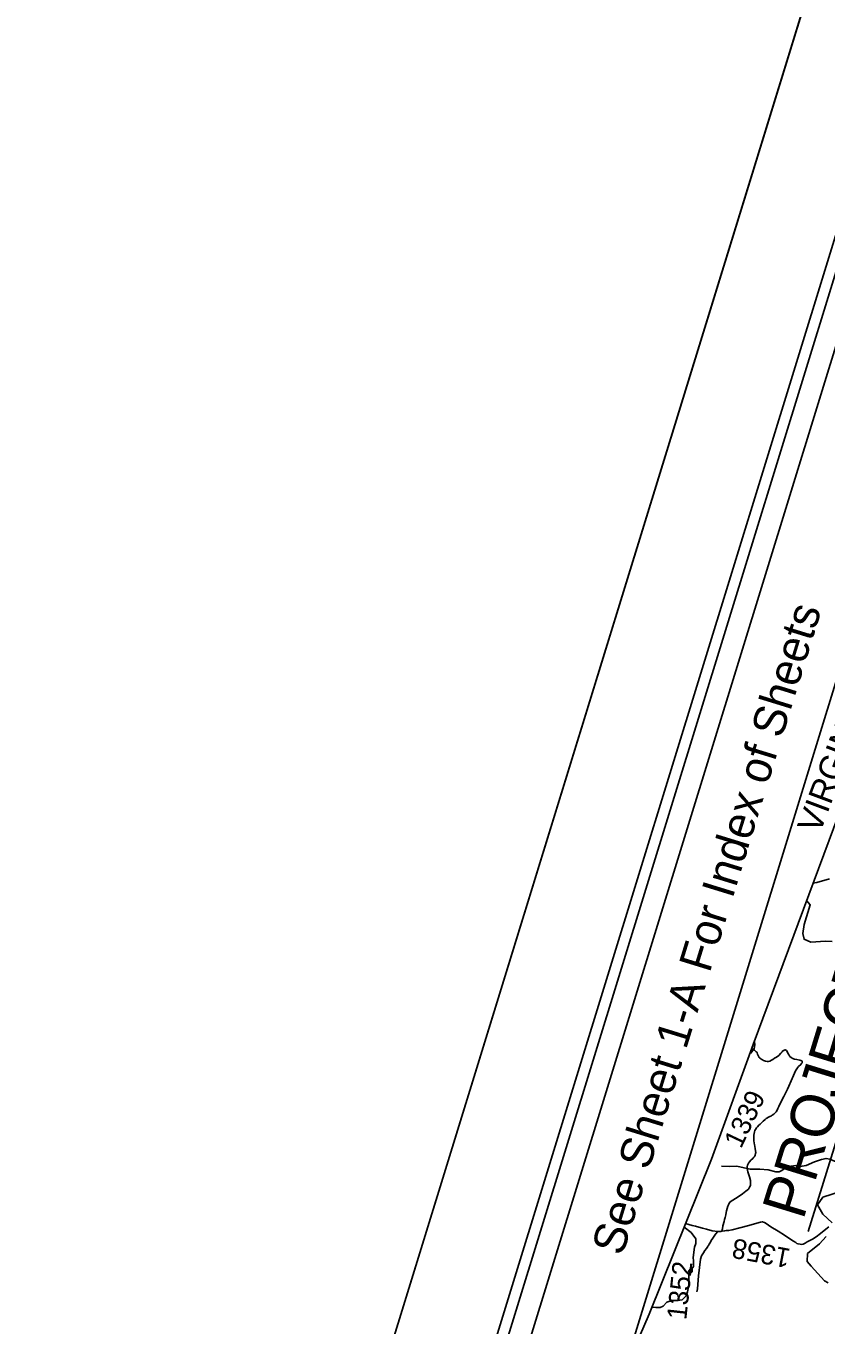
# Model space of a CAD drawing. Extents: x 1347947 to 1350662, y 1027710 to 1030532.
# Drawn here: x 1347946.9 to 1348130.6, y 1028835.1 to 1029133.4 of the extents above; entities that cross this region are included whole.
import ezdxf

# ---------------------------------------------------------------- set-up
doc = ezdxf.new("R2010")
doc.units = 0
for name, color, linetype in [('Default', 7, 'Continuous'), ('Prop Leader Line Light', 7, 'Continuous'), ('Prop Leader Line Medium', 7, 'Continuous'), ('Prop WCC CELL', 7, 'Continuous'), ('Sheet Cutting Line CELL', 7, 'Continuous'), ('Sheet Data Field CELL', 7, 'Continuous'), ('Sheet Plot Border Inside CELL', 7, 'Continuous'), ('Sheet Plot Border Outside CELL', 7, 'Continuous'), ('Sheet Title CELL', 7, 'Continuous')]:
    doc.layers.add(name, color=color, linetype=linetype)

msp = doc.modelspace()

# ---------------------------------------------------------------- linework, layer by layer
at = {"layer": 'Default'}
msp.add_line((1348099.77, 1028848.03), (1348099.39, 1028847.22), dxfattribs=at)
for points in [[(1348083.52, 1028822.71), (1348089.97, 1028837.63), (1348104.26, 1028873.21), (1348113.82, 1028899.5), (1348162.49, 1029030.38), (1348171.57, 1029045.86), (1348180.52, 1029067.26), (1348186.85, 1029082.58), (1348194.68, 1029101.03), (1348199.8, 1029113.4)], [(1348131.38, 1028937.53), (1348128.47, 1028936.69), (1348127.59, 1028936.53)], [(1348131.99, 1028923.18), (1348130.49, 1028923.2), (1348127.12, 1028923.01), (1348125.54, 1028923.66), (1348125.22, 1028924.96), (1348125.55, 1028927.05), (1348126.95, 1028931.57), (1348126.11, 1028932.56)], [(1348113.12, 1028897.57), (1348113.32, 1028897.55), (1348114.06, 1028898.62), (1348114.24, 1028899.43), (1348114.12, 1028900.13), (1348114.1, 1028900.17)], [(1348106.66, 1028856.63), (1348106.77, 1028857.22), (1348106.92, 1028857.86), (1348107.17, 1028858.89), (1348107.29, 1028859.32), (1348107.41, 1028859.77), (1348107.55, 1028860.39), (1348107.67, 1028860.95), (1348107.76, 1028861.29), (1348107.9, 1028861.86), (1348108.05, 1028862.37), (1348108.17, 1028862.73), (1348108.25, 1028862.93), (1348108.38, 1028863.15), (1348108.57, 1028863.37), (1348109.78, 1028864.16), (1348110.61, 1028864.72), (1348111.4, 1028865.23), (1348112.18, 1028865.82), (1348112.75, 1028866.31), (1348112.89, 1028866.48), (1348113.04, 1028866.74), (1348113.14, 1028867), (1348113.21, 1028867.24), (1348113.26, 1028867.54), (1348113.25, 1028867.8), (1348113.2, 1028868.25), (1348112.98, 1028869.09), (1348112.6, 1028870.3), (1348112.48, 1028871.06), (1348112.5, 1028871.43), (1348112.54, 1028871.82), (1348112.59, 1028871.96), (1348112.67, 1028872.12), (1348112.78, 1028872.3), (1348112.97, 1028872.57), (1348113.34, 1028872.94), (1348113.74, 1028873.32), (1348114.01, 1028873.61), (1348114.21, 1028873.9), (1348114.31, 1028874.09), (1348114.41, 1028874.45), (1348114.44, 1028874.72), (1348114.34, 1028875.53), (1348114.2, 1028876.13), (1348114.12, 1028876.46), (1348114.06, 1028876.9), (1348114.02, 1028877.37), (1348114, 1028877.89), (1348114.02, 1028878.39), (1348114.03, 1028878.66), (1348114.09, 1028879.08), (1348114.16, 1028879.43), (1348114.26, 1028879.76), (1348114.36, 1028880.01), (1348114.6, 1028880.36), (1348114.84, 1028880.63), (1348115.16, 1028880.95), (1348115.47, 1028881.25), (1348116.17, 1028881.88), (1348116.57, 1028882.27), (1348116.85, 1028882.49), (1348117.49, 1028882.88), (1348117.7, 1028882.96), (1348118.05, 1028883.15), (1348118.24, 1028883.25), (1348118.6, 1028883.51), (1348118.92, 1028883.82), (1348119.1, 1028884.06), (1348119.36, 1028884.47), (1348119.5, 1028884.8), (1348119.74, 1028885.31), (1348119.96, 1028885.79), (1348120.86, 1028887.57), (1348121.71, 1028889.29), (1348122.02, 1028889.97), (1348123.07, 1028892.38), (1348123.58, 1028893.45), (1348123.99, 1028894.15), (1348124.28, 1028894.46), (1348124.76, 1028894.9), (1348124.95, 1028895.11), (1348125.09, 1028895.28), (1348125.11, 1028895.48), (1348125.07, 1028895.63), (1348124.99, 1028895.75), (1348124.79, 1028895.87), (1348124.55, 1028895.93), (1348123.89, 1028896.04), (1348123.37, 1028896.16), (1348123.12, 1028896.23), (1348122.77, 1028896.39), (1348122.58, 1028896.51), (1348122.3, 1028896.78), (1348122.09, 1028897.03), (1348121.89, 1028897.35), (1348121.7, 1028897.76), (1348121.51, 1028898.12), (1348121.38, 1028898.23), (1348121.28, 1028898.27), (1348121.16, 1028898.28), (1348121, 1028898.24), (1348120.87, 1028898.16), (1348120.69, 1028898.02), (1348120.52, 1028897.85), (1348120.22, 1028897.53), (1348119.76, 1028897.01), (1348119.19, 1028896.6), (1348118.73, 1028896.34), (1348118.34, 1028896.07), (1348118.09, 1028895.91), (1348117.7, 1028895.67), (1348117.34, 1028895.59), (1348117.06, 1028895.59)], [(1348117.06, 1028895.59), (1348116.65, 1028895.69), (1348116.42, 1028895.77), (1348116.2, 1028895.87), (1348115.99, 1028895.96), (1348115.82, 1028896.06), (1348115.63, 1028896.19), (1348115.51, 1028896.27), (1348115.39, 1028896.39), (1348115.26, 1028896.55), (1348114.88, 1028897.32), (1348114.74, 1028897.59), (1348114.66, 1028897.75), (1348114.56, 1028897.85), (1348114.38, 1028897.99), (1348114.12, 1028898.18), (1348113.78, 1028898.39), (1348113.49, 1028898.6)], [(1348134.34, 1028873.53), (1348133.48, 1028872.71), (1348132.53, 1028872.74), (1348131.46, 1028873.17), (1348130.58, 1028873.34), (1348129.53, 1028873.1), (1348127.96, 1028872.56), (1348126.04, 1028871.75), (1348124.62, 1028871.47), (1348123.63, 1028871.72), (1348122.61, 1028871.56), (1348121.07, 1028871.04), (1348120.4, 1028870.6), (1348119.83, 1028870.29), (1348119.08, 1028870.31), (1348117.32, 1028870.72), (1348115.35, 1028870.92), (1348113.14, 1028870.9), (1348111.77, 1028871.18), (1348110.07, 1028871.57), (1348108.5, 1028871.51), (1348106.6, 1028871.6)], [(1348132.01, 1028858.54), (1348129.81, 1028860.58), (1348128.61, 1028862.68), (1348129.88, 1028864.48), (1348133.89, 1028865.78)], [(1348099.77, 1028848.03), (1348100.12, 1028848.56), (1348100.12, 1028849.84), (1348100.07, 1028850.57), (1348100.4, 1028852.97), (1348100.65, 1028853.84), (1348100.68, 1028854.91), (1348099.64, 1028856.31), (1348097.98, 1028857.57)], [(1348105.77, 1028856.57), (1348104.47, 1028856.75), (1348103.13, 1028857.09), (1348102.2, 1028857.32), (1348101.36, 1028857.55), (1348100.64, 1028857.76), (1348099.83, 1028857.97), (1348098.32, 1028858.43)], [(1348131.19, 1028857.62), (1348130.14, 1028856.82), (1348129.27, 1028856.15), (1348128.29, 1028855.37), (1348127.44, 1028854.83), (1348126.68, 1028854.42), (1348126.25, 1028854.18), (1348125.79, 1028853.9), (1348125.35, 1028853.7), (1348125.03, 1028853.62), (1348124.64, 1028853.64), (1348124.17, 1028853.73), (1348123.9, 1028853.85), (1348123.63, 1028854.02), (1348123.1, 1028854.35), (1348122.06, 1028855.07), (1348121.01, 1028855.71), (1348119.57, 1028856.62), (1348117.91, 1028857.68), (1348116.8, 1028858.41), (1348116.42, 1028858.61), (1348116.16, 1028858.72), (1348116.05, 1028858.76), (1348115.93, 1028858.76), (1348115.52, 1028858.72), (1348114.72, 1028858.5), (1348112.87, 1028857.98), (1348110.77, 1028857.42), (1348109.03, 1028856.98), (1348108.2, 1028856.78), (1348107.68, 1028856.77), (1348107.3, 1028856.69), (1348106.66, 1028856.63)], [(1348105.77, 1028856.57), (1348105.22, 1028855.98), (1348104.59, 1028855.02), (1348104.23, 1028854.47), (1348104.03, 1028854.13), (1348103.86, 1028853.89), (1348103.74, 1028853.66), (1348103.63, 1028853.52), (1348103.56, 1028853.38), (1348103.46, 1028853.23), (1348103.33, 1028852.99), (1348103.27, 1028852.93), (1348103.13, 1028852.69), (1348102.78, 1028852.18), (1348102.46, 1028851.71), (1348102.27, 1028851.44), (1348102.02, 1028850.96), (1348101.77, 1028850.2), (1348101.29, 1028846.4), (1348101.04, 1028843.38), (1348101.01, 1028843.06), (1348100.94, 1028842.69)], [(1348106.66, 1028856.63), (1348106.41, 1028856.6), (1348106.16, 1028856.6), (1348105.98, 1028856.59), (1348105.77, 1028856.57)], [(1348131.07, 1028844.81), (1348130.23, 1028845.28), (1348127.16, 1028848.64), (1348126.23, 1028849.71), (1348126.34, 1028851.51), (1348129.09, 1028853.77), (1348130.6, 1028855.41)], [(1348099.39, 1028847.22), (1348099.03, 1028847.35), (1348099.09, 1028847.53), (1348099.47, 1028847.97), (1348099.7, 1028848.03), (1348099.77, 1028848.03)], [(1348099.39, 1028847.22), (1348099.03, 1028847.35), (1348099.09, 1028847.53), (1348099.47, 1028847.97), (1348099.7, 1028848.03), (1348099.77, 1028848.03)], [(1348099.04, 1028844.41), (1348099.08, 1028846.52), (1348099.39, 1028847.22)], [(1348099.77, 1028848.03), (1348099.85, 1028847.88), (1348099.87, 1028847.42), (1348099.73, 1028847.21), (1348099.39, 1028847.22)], [(1348090.65, 1028839.17), (1348091.53, 1028839.1), (1348092.46, 1028839.15), (1348093.22, 1028839.43), (1348093.99, 1028840.35), (1348095.24, 1028840.72), (1348096.57, 1028840.73), (1348097.51, 1028840.91), (1348098.43, 1028841.81), (1348098.75, 1028842.72), (1348098.97, 1028843.76), (1348099.04, 1028844.41)]]:
    msp.add_lwpolyline(points, dxfattribs=at)
at = {"layer": 'Prop Leader Line Medium'}
msp.add_line((1348144.09, 1028913.43), (1348126.44, 1028856.54), dxfattribs=at)
at = {"layer": 'Prop WCC CELL'}
msp.add_line((1348175.36, 1029120.93), (1348067.18, 1028769.65), dxfattribs=at)
at = {"layer": 'Sheet Cutting Line CELL'}
msp.add_line((1347946.88, 1028557.97), (1348442.51, 1030167.38), dxfattribs=at)
at = {"layer": 'Sheet Plot Border Inside CELL'}
msp.add_lwpolyline([(1348980.53, 1028253.25), (1349471, 1029845.94), (1348462.64, 1030156.47), (1347972.16, 1028563.78)], close=True, dxfattribs=at)
at = {"layer": 'Sheet Plot Border Outside CELL'}
msp.add_lwpolyline([(1348442.51, 1030167.38), (1347946.88, 1028557.97), (1348998.14, 1028234.22), (1349493.77, 1029843.63)], close=True, dxfattribs=at)
at = {"layer": 'Sheet Title CELL'}
for points in [[(1348458.46, 1030134.23), (1348022.85, 1028719.76)], [(1348461.76, 1030127.97), (1348043.83, 1028770.87)]]:
    msp.add_lwpolyline(points, dxfattribs=at)

# ---------------------------------------------------------------- texts
at = {"layer": 'Prop Leader Line Light'}
for s, rotation, p in [('1339', 64.7439, (1348111.05, 1028875.42)), ('1358', 169.1883, (1348122.65, 1028852.52)), ('1352', 83.8944, (1348098.48, 1028836.15))]:
    msp.add_text(s, height=4.5, rotation=rotation, dxfattribs=at).set_placement(p)
at = {"layer": 'Sheet Data Field CELL'}
for s, height, rotation, p in [('VIRGINIA STATE LINE', 5.625, 69.5056, (1348129.13, 1028947.7)), ('VIRGINIA STATE LINE', 5.625, 69.5056, (1348129.13, 1028947.7)), ('PROJECT', 10, 72.8834, (1348125.32, 1028859.01))]:
    msp.add_text(s, height=height, rotation=rotation, dxfattribs=at).set_placement(p)
at = {"layer": 'Sheet Title CELL'}
msp.add_text('See Sheet 1-A For Index of Sheets', height=7.5, rotation=72.8834, dxfattribs=at).set_placement((1348083.81, 1028850.73))

doc.saveas('drawing.dxf')
